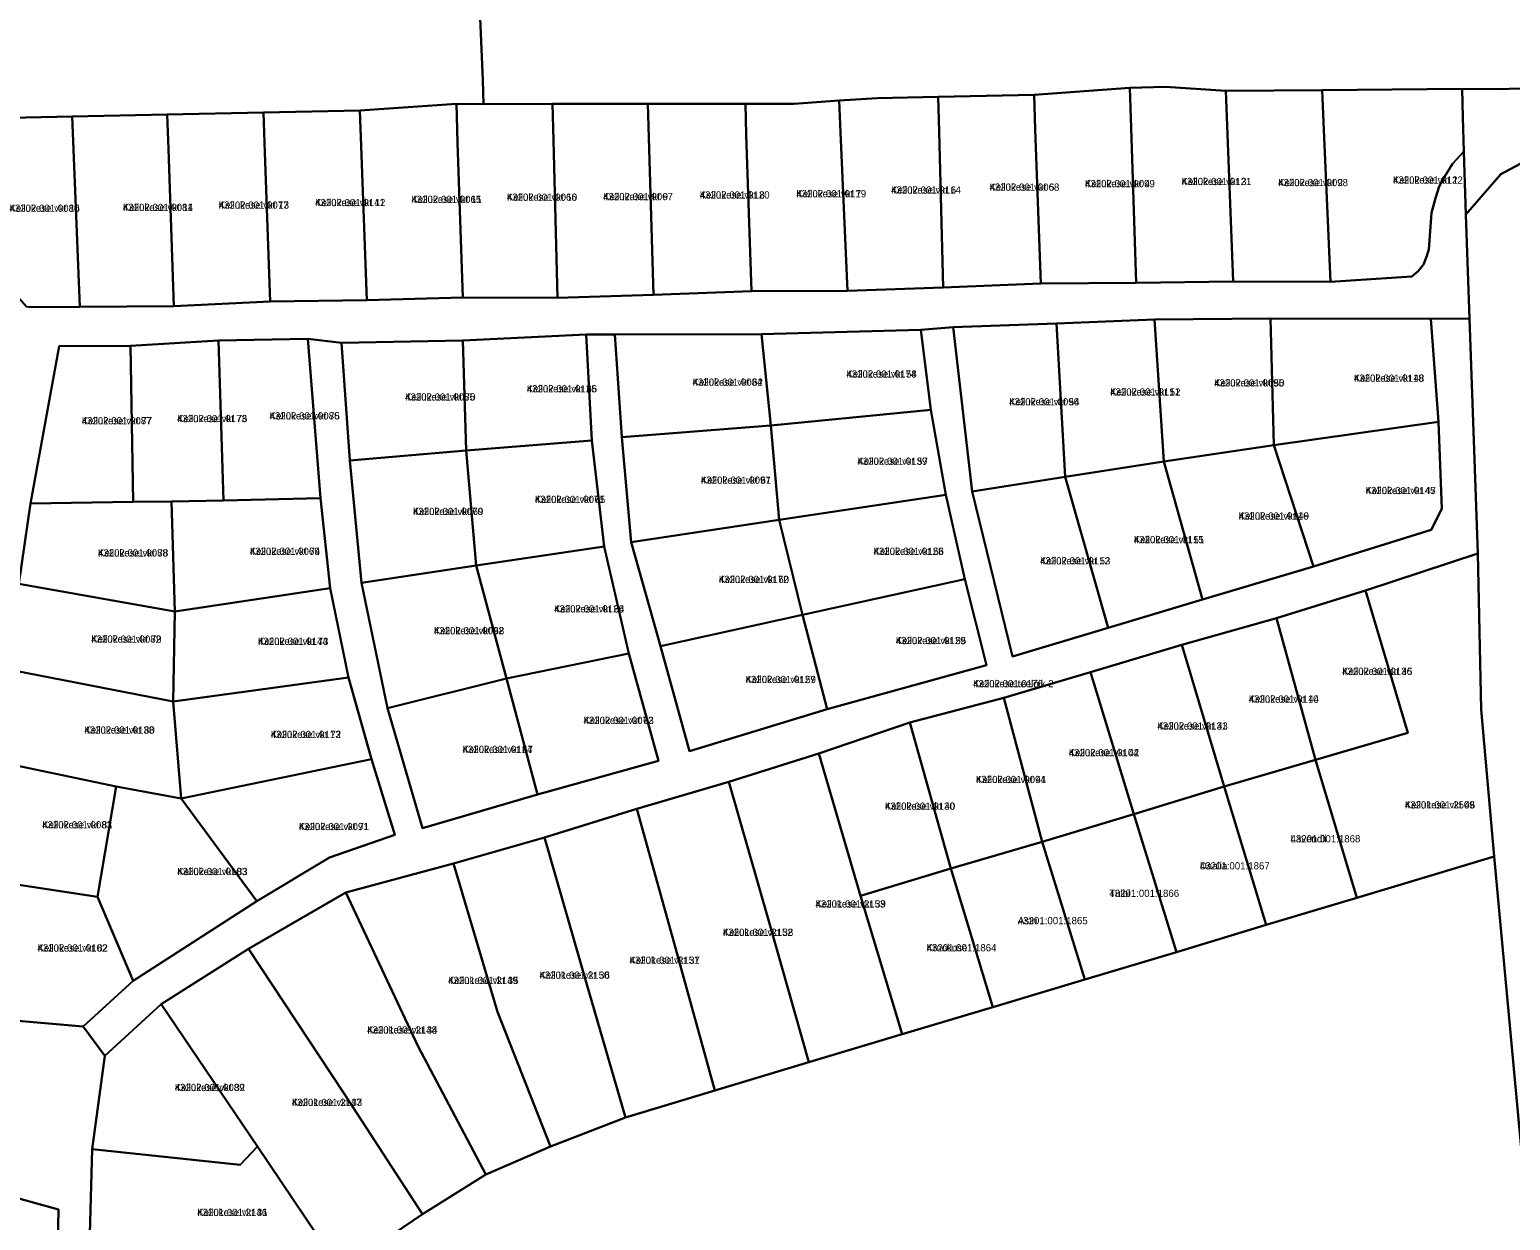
# Model space of a CAD drawing. Extents: x 661852 to 683758, y 6469495 to 6482657.
# Drawn here: x 665720.1 to 666027.7, y 6471512.2 to 6471759.5 of the extents above; entities that cross this region are included whole.
import ezdxf

# ---------------------------------------------------------------- set-up
doc = ezdxf.new("R2010")
doc.units = 0
for name, color, linetype in [('L_AADRESS', 7, 'Continuous'), ('PIIR', 7, 'Continuous'), ('TUNNUS', 7, 'Continuous')]:
    doc.layers.add(name, color=color, linetype=linetype)

msp = doc.modelspace()

# ---------------------------------------------------------------- linework, layer by layer
at = {"layer": 'PIIR'}
for points in [[(665812.89, 6471779.74), (665814.19, 6471749.05), (665814.38, 6471744.07), (665808.72, 6471744.08), (665788.69, 6471742.75), (665768.63, 6471742.33), (665748.66, 6471741.91), (665728.91, 6471741.5), (665693.53, 6471740.75), (665686.99, 6471739.11), (665686.19, 6471738.96), (665684.92, 6471737.76), (665684.4, 6471741.78), (665672.39, 6471830.94)], [(666188.02, 6471764.83), (666128.13, 6471758.72), (666113.14, 6471755.77), (666050.75, 6471747.95), (666025.02, 6471747.15), (666017.63, 6471747.2), (665988.57, 6471746.94), (665968.56, 6471746.79), (665956.01, 6471747.64), (665948.6, 6471747.42), (665928.71, 6471745.98), (665908.82, 6471745.56), (665896.11, 6471745.3), (665888.22, 6471744.84), (665878.88, 6471744.1), (665868.75, 6471744.1), (665848.52, 6471744.09), (665828.69, 6471744.08), (665814.38, 6471744.07), (665814.19, 6471749.05), (665812.89, 6471779.74)], [(665719.91, 6471701.87), (665730.5, 6471701.93), (665750.04, 6471702.1), (665770.07, 6471703.06), (665790.12, 6471703.32), (665810.09, 6471703.93), (665829.73, 6471703.84), (665849.7, 6471704.44), (665870.04, 6471705.23), (665889.94, 6471705.28), (665909.81, 6471705.96), (665930.12, 6471706.78), (665949.89, 6471706.94), (665970.09, 6471707.22), (665990.27, 6471707.12), (666007.18, 6471708.27), (666008.51, 6471709.36), (666009.57, 6471710.73), (666010.26, 6471712.33), (666010.68, 6471713.89), (666011.26, 6471721.47), (666012.08, 6471724.55), (666012.85, 6471726.94), (666013.95, 6471728.98), (666015.61, 6471731.65), (666017.96, 6471734.19), (666018.41, 6471721.13), (666019.17, 6471699.51), (666011.1, 6471699.5), (665977.85, 6471699.55), (665953.7, 6471699.36), (665933.37, 6471698.49), (665911.89, 6471697.72), (665905.17, 6471697.16), (665872.12, 6471696.29), (665841.66, 6471696.19), (665835.7, 6471696.23), (665810.06, 6471694.98), (665784.88, 6471694.49), (665777.87, 6471695.33), (665759.33, 6471694.97), (665741.07, 6471693.86), (665726.19, 6471693.81), (665720.26, 6471661.11), (665717.86, 6471644.43)], [(665784.67, 6471501.96), (665801.72, 6471513.57), (665814.83, 6471521.75), (665828.25, 6471527.62), (665843.84, 6471533.6), (665862.39, 6471539.22), (665881.96, 6471545.09), (665901.3, 6471550.89), (665920.12, 6471556.52), (665939.25, 6471562.26), (665958.29, 6471567.98), (665976.92, 6471573.6), (665995.76, 6471579.25), (666024.31, 6471587.84), (666030.99, 6471515.35)], [(665702.43, 6471554.99), (665731.2, 6471552.53), (665735.71, 6471546.41), (665733.06, 6471527.07), (665732.32, 6471499.43)], [(665725.28, 6471473.59), (665726.1, 6471514.53), (665717.83, 6471516.78)]]:
    msp.add_lwpolyline(points, dxfattribs=at)
for points in [[(666017.63, 6471747.2), (666025.02, 6471747.15), (666050.75, 6471747.95), (666113.14, 6471755.77), (666128.13, 6471758.72), (666188.02, 6471764.83), (666192.34, 6471742.07), (666186.44, 6471748), (666177.54, 6471750.16), (666147.11, 6471747.24), (666103.66, 6471742.46), (666035.88, 6471735), (666025.65, 6471729.5), (666018.41, 6471721.13), (666017.96, 6471734.19), (666017.77, 6471741.3)], [(665909.81, 6471705.96), (665909, 6471738.38), (665908.82, 6471745.56), (665928.71, 6471745.98), (665928.97, 6471738.76), (665930.11, 6471706.78)], [(665930.11, 6471706.78), (665928.97, 6471738.76), (665928.71, 6471745.98), (665948.6, 6471747.42), (665948.91, 6471739.16), (665949.89, 6471706.94)], [(665949.89, 6471706.94), (665948.91, 6471739.16), (665948.6, 6471747.42), (665956.01, 6471747.64), (665968.56, 6471746.79), (665968.83, 6471739.62), (665970.09, 6471707.22)], [(665970.09, 6471707.22), (665968.83, 6471739.62), (665968.56, 6471746.79), (665988.57, 6471746.94), (665988.85, 6471740.33), (665990.27, 6471707.12)], [(665990.27, 6471707.12), (665988.85, 6471740.33), (665988.57, 6471746.94), (666017.63, 6471747.2), (666017.77, 6471741.3), (666017.96, 6471734.19), (666015.61, 6471731.65), (666013.95, 6471728.98), (666012.85, 6471726.94), (666012.08, 6471724.55), (666011.26, 6471721.47), (666010.68, 6471713.89), (666010.26, 6471712.33), (666009.57, 6471710.73), (666008.51, 6471709.36), (666007.18, 6471708.27)], [(665770.07, 6471703.06), (665768.94, 6471734.02), (665768.63, 6471742.33), (665788.69, 6471742.75), (665788.96, 6471735.32), (665790.12, 6471703.32)], [(665790.12, 6471703.32), (665788.96, 6471735.32), (665788.69, 6471742.75), (665808.72, 6471744.08), (665808.96, 6471736.03), (665810.09, 6471703.93)], [(665810.09, 6471703.93), (665808.96, 6471736.03), (665808.72, 6471744.08), (665814.38, 6471744.07), (665828.69, 6471744.08), (665828.9, 6471736.49), (665829.73, 6471703.84)], [(665829.73, 6471703.84), (665828.9, 6471736.49), (665828.69, 6471744.08), (665848.52, 6471744.09), (665848.73, 6471737.02), (665849.7, 6471704.44)], [(665849.7, 6471704.44), (665848.73, 6471737.02), (665848.52, 6471744.09), (665868.75, 6471744.1), (665868.95, 6471737.65), (665870.04, 6471705.23)], [(665889.94, 6471705.28), (665870.04, 6471705.23), (665868.95, 6471737.65), (665868.75, 6471744.1), (665878.88, 6471744.1), (665888.22, 6471744.84), (665888.51, 6471738.14)], [(665889.94, 6471705.28), (665888.51, 6471738.14), (665888.22, 6471744.84), (665896.11, 6471745.3), (665908.82, 6471745.56), (665909, 6471738.38), (665909.81, 6471705.96)], [(665719.91, 6471701.87), (665719.44, 6471701.97), (665691.18, 6471734.14), (665686.99, 6471739.11), (665693.53, 6471740.75), (665728.91, 6471741.5), (665729.19, 6471734.62), (665730.5, 6471701.93)], [(665730.5, 6471701.93), (665729.19, 6471734.62), (665728.91, 6471741.5), (665748.66, 6471741.91), (665748.91, 6471734.69), (665750.04, 6471702.1)], [(665750.04, 6471702.1), (665748.91, 6471734.69), (665748.66, 6471741.91), (665768.63, 6471742.33), (665768.94, 6471734.02), (665770.07, 6471703.06)], [(666019.17, 6471699.51), (666018.41, 6471721.13), (666025.65, 6471729.5), (666035.88, 6471735), (666103.66, 6471742.46), (666119.96, 6471639.91), (666134.37, 6471549.3), (666030.99, 6471515.35), (666024.31, 6471587.84), (666021.56, 6471618.31), (666020.87, 6471650.74)], [(665741.58, 6471562.02), (665767.3, 6471578.54), (665782.4, 6471587.6), (665795.91, 6471592.33), (665791.07, 6471608.04), (665786.35, 6471624.99), (665782.48, 6471643.51), (665780.53, 6471662.23), (665777.87, 6471695.33), (665784.88, 6471694.49), (665786.57, 6471670.02), (665788.99, 6471644.66), (665794.44, 6471618.63), (665801.67, 6471593.69), (665825.6, 6471600.66), (665850.7, 6471607.71), (665844.52, 6471630), (665839.41, 6471652.22), (665836.83, 6471674.23), (665835.7, 6471696.23), (665841.66, 6471696.19), (665843.06, 6471674.86), (665845.06, 6471653.09), (665851.14, 6471631.5), (665857.14, 6471609.7), (665885.76, 6471618.43), (665918.86, 6471627.53), (665914.34, 6471645.39), (665910.41, 6471662.92), (665907.27, 6471680.57), (665905.17, 6471697.16), (665911.89, 6471697.72), (665915.83, 6471663.61), (665924.21, 6471629.38), (665944.1, 6471635.31), (665963.69, 6471641.15), (665986.77, 6471648.03), (666011.2, 6471655.66), (666013.43, 6471660.01), (666012.75, 6471678.11), (666011.1, 6471699.5), (666019.17, 6471699.51), (666020.87, 6471650.74), (665997.58, 6471643.03), (665979.06, 6471637.28), (665959.44, 6471631.79), (665940.45, 6471626.06), (665922.46, 6471620.79), (665902.92, 6471615.62), (665884.04, 6471609.17), (665865.35, 6471603.3), (665846.22, 6471597.68), (665827, 6471591.75), (665808.13, 6471586.34), (665785.75, 6471580.31), (665765.56, 6471568.66), (665747.38, 6471557.17), (665735.71, 6471546.41), (665731.2, 6471552.53)], [(665907.27, 6471680.57), (665874.07, 6471677.35), (665872.12, 6471696.29), (665905.17, 6471697.16)], [(665933.37, 6471698.49), (665935.2, 6471666.68), (665915.83, 6471663.61), (665911.89, 6471697.72)], [(665953.7, 6471699.36), (665955.67, 6471669.82), (665935.2, 6471666.68), (665933.37, 6471698.49)], [(665977.85, 6471699.55), (665978.52, 6471673.25), (665955.67, 6471669.82), (665953.7, 6471699.36)], [(666011.1, 6471699.5), (666012.75, 6471678.11), (665978.52, 6471673.25), (665977.85, 6471699.55)], [(665726.19, 6471693.81), (665741.07, 6471693.86), (665741.56, 6471661.43), (665720.26, 6471661.11)], [(665759.33, 6471694.97), (665760.35, 6471661.74), (665749.56, 6471661.56), (665741.56, 6471661.43), (665741.07, 6471693.86)], [(665777.87, 6471695.33), (665780.53, 6471662.23), (665760.35, 6471661.74), (665759.33, 6471694.97)], [(665784.88, 6471694.49), (665810.06, 6471694.98), (665810.75, 6471672.15), (665786.57, 6471670.02)], [(665835.7, 6471696.23), (665836.83, 6471674.23), (665810.75, 6471672.15), (665810.06, 6471694.98)], [(665841.66, 6471696.19), (665872.12, 6471696.29), (665874.07, 6471677.35), (665843.06, 6471674.86)], [(665910.41, 6471662.92), (665875.74, 6471657.72), (665874.07, 6471677.35), (665907.27, 6471680.57)], [(665843.06, 6471674.86), (665874.07, 6471677.35), (665875.74, 6471657.72), (665845.06, 6471653.09)], [(665986.77, 6471648.03), (665978.52, 6471673.25), (666012.75, 6471678.11), (666013.43, 6471660.01), (666011.2, 6471655.66)], [(665786.57, 6471670.02), (665810.75, 6471672.15), (665812.87, 6471648.21), (665788.99, 6471644.66)], [(665839.41, 6471652.22), (665812.87, 6471648.21), (665810.75, 6471672.15), (665836.83, 6471674.23)], [(665963.69, 6471641.15), (665955.67, 6471669.82), (665978.52, 6471673.25), (665986.77, 6471648.03)], [(665944.1, 6471635.31), (665935.2, 6471666.68), (665955.67, 6471669.82), (665963.69, 6471641.15)], [(665915.83, 6471663.61), (665935.2, 6471666.68), (665944.1, 6471635.31), (665924.21, 6471629.38)], [(665914.34, 6471645.39), (665880.65, 6471637.97), (665875.74, 6471657.72), (665910.41, 6471662.92)], [(665720.26, 6471661.11), (665741.56, 6471661.43), (665749.56, 6471661.56), (665750.25, 6471638.66), (665717.85, 6471644.43)], [(665782.48, 6471643.51), (665750.25, 6471638.66), (665749.56, 6471661.56), (665760.35, 6471661.74), (665780.53, 6471662.23)], [(665845.06, 6471653.09), (665875.74, 6471657.72), (665880.65, 6471637.97), (665851.14, 6471631.5)], [(665844.52, 6471630), (665819.14, 6471624.77), (665812.87, 6471648.21), (665839.41, 6471652.22)], [(666006.35, 6471613.51), (665997.58, 6471643.03), (666020.87, 6471650.74), (666021.56, 6471618.31), (666024.31, 6471587.84), (665995.76, 6471579.25), (665987.16, 6471607.88)], [(665788.99, 6471644.66), (665812.87, 6471648.21), (665819.14, 6471624.77), (665794.44, 6471618.63)], [(665717.85, 6471644.43), (665750.25, 6471638.66), (665749.89, 6471619.98), (665714.66, 6471626.82)], [(665885.76, 6471618.43), (665880.65, 6471637.97), (665914.34, 6471645.39), (665918.86, 6471627.53)], [(665786.35, 6471624.99), (665749.89, 6471619.98), (665750.25, 6471638.66), (665782.48, 6471643.51)], [(665987.16, 6471607.88), (665979.06, 6471637.28), (665997.58, 6471643.03), (666006.35, 6471613.51)], [(665851.14, 6471631.5), (665880.65, 6471637.97), (665885.76, 6471618.43), (665857.14, 6471609.7)], [(665968.23, 6471602.38), (665959.44, 6471631.79), (665979.06, 6471637.28), (665987.16, 6471607.88)], [(665825.6, 6471600.66), (665819.14, 6471624.77), (665844.52, 6471630), (665850.7, 6471607.71)], [(665949.41, 6471596.57), (665940.45, 6471626.06), (665959.44, 6471631.79), (665968.23, 6471602.38)], [(665714.66, 6471626.82), (665749.89, 6471619.98), (665751.55, 6471599.84), (665738.07, 6471602.37), (665711.59, 6471607.86)], [(665930.38, 6471590.89), (665922.46, 6471620.79), (665940.45, 6471626.06), (665949.41, 6471596.57)], [(665791.07, 6471608.04), (665751.55, 6471599.84), (665749.89, 6471619.98), (665786.35, 6471624.99)], [(665801.67, 6471593.69), (665794.44, 6471618.63), (665819.14, 6471624.77), (665825.6, 6471600.66)], [(665911.45, 6471585.35), (665902.92, 6471615.62), (665922.46, 6471620.79), (665930.38, 6471590.89)], [(665892.69, 6471579.66), (665884.04, 6471609.17), (665902.92, 6471615.62), (665911.45, 6471585.35)], [(665711.59, 6471607.86), (665738.07, 6471602.37), (665734.21, 6471579.45), (665706.84, 6471583.61)], [(665782.4, 6471587.6), (665767.3, 6471578.54), (665751.55, 6471599.84), (665791.07, 6471608.04), (665795.91, 6471592.33)], [(665873.65, 6471574.37), (665865.35, 6471603.3), (665884.04, 6471609.17), (665892.69, 6471579.66), (665901.3, 6471550.89), (665881.96, 6471545.09)], [(665976.92, 6471573.6), (665968.23, 6471602.38), (665987.16, 6471607.88), (665995.76, 6471579.25)], [(665741.58, 6471562.02), (665734.21, 6471579.45), (665738.07, 6471602.37), (665751.55, 6471599.84), (665767.3, 6471578.54)], [(665854.29, 6471568.57), (665846.22, 6471597.68), (665865.35, 6471603.3), (665873.65, 6471574.37), (665881.96, 6471545.09), (665862.39, 6471539.22)], [(665958.29, 6471567.98), (665949.41, 6471596.57), (665968.23, 6471602.38), (665976.92, 6471573.6)], [(665835.7, 6471561.73), (665827, 6471591.75), (665846.22, 6471597.68), (665854.29, 6471568.57), (665862.39, 6471539.22), (665843.84, 6471533.6)], [(665939.25, 6471562.26), (665930.38, 6471590.89), (665949.41, 6471596.57), (665958.29, 6471567.98)], [(665817.3, 6471555.57), (665808.13, 6471586.34), (665827, 6471591.75), (665835.7, 6471561.73), (665843.84, 6471533.6), (665828.25, 6471527.62)], [(665920.12, 6471556.52), (665911.45, 6471585.35), (665930.38, 6471590.89), (665939.25, 6471562.26)], [(665800.81, 6471548.37), (665785.75, 6471580.31), (665808.13, 6471586.34), (665817.3, 6471555.57), (665828.25, 6471527.62), (665814.83, 6471521.75)], [(665706.84, 6471583.61), (665734.21, 6471579.45), (665741.58, 6471562.02), (665731.2, 6471552.53), (665702.43, 6471554.99)], [(665901.3, 6471550.89), (665892.69, 6471579.66), (665911.45, 6471585.35), (665920.12, 6471556.52)], [(665785.32, 6471538.68), (665765.56, 6471568.66), (665785.75, 6471580.31), (665800.81, 6471548.37), (665814.83, 6471521.75), (665801.72, 6471513.57)], [(665767.41, 6471527.59), (665747.38, 6471557.17), (665765.56, 6471568.66), (665785.32, 6471538.68), (665801.72, 6471513.57), (665784.67, 6471501.96)], [(665735.71, 6471546.41), (665747.38, 6471557.17), (665767.41, 6471527.59), (665763.85, 6471523.8), (665733.06, 6471527.07)], [(665732.32, 6471499.43), (665733.06, 6471527.07), (665763.85, 6471523.8), (665767.41, 6471527.59), (665784.67, 6471501.96), (665779.93, 6471498.71), (665759.93, 6471499.05)], [(665726.1, 6471514.53), (665725.28, 6471473.59), (665701.12, 6471486.1), (665696.35, 6471486.42), (665717.83, 6471516.78)]]:
    msp.add_lwpolyline(points, close=True, dxfattribs=at)

# ---------------------------------------------------------------- texts
at = {"layer": 'L_AADRESS'}
for s, p in [('Kellukese vkt 5', (665919.46, 6471726.07)), ('Kellukese vkt 4', (665939.3, 6471726.8)), ('Kellukese vkt 3', (665959.35, 6471727.24)), ('Kellukese vkt 2', (665979.42, 6471727.02)), ('Kellukese vkt 1', (666003.27, 6471727.54)), ('Kellukese vkt 12', (665779.38, 6471722.87)), ('Kellukese vkt 11', (665799.39, 6471723.53)), ('Kellukese vkt 10', (665819.22, 6471723.98)), ('Kellukese vkt 9', (665839.2, 6471724.1)), ('Kellukese vkt 8', (665859.28, 6471724.45)), ('Kellukese vkt 7', (665879.34, 6471724.7)), ('Kellukese vkt 6', (665899.02, 6471725.47)), ('Kellukese vkt 15', (665715.91, 6471721.69)), ('Kellukese vkt 14', (665739.47, 6471721.86)), ('Kellukese vkt 13', (665759.36, 6471722.34)), ('Kellukese vkt 58', (665889.74, 6471687.26)), ('Kellukese vkt 48', (665995.15, 6471686.4)), ('Kellukese vkt 66', (665823.35, 6471684.19)), ('Kellukese vkt 62', (665857.79, 6471685.57)), ('Kellukese vkt 52', (665944.52, 6471683.54)), ('Kellukese vkt 50', (665966.11, 6471685.42)), ('Kellukese vkt 70', (665798.07, 6471682.5)), ('Kellukese vkt 54', (665923.55, 6471681.49)), ('Kellukese vkt 77', (665730.91, 6471677.55)), ('Kellukese vkt 76', (665750.71, 6471678.01)), ('Kellukese vkt 75', (665769.93, 6471678.57)), ('Kellukese vkt 57', (665892.04, 6471669.15)), ('Kellukese vkt 61', (665859.52, 6471665.22)), ('Kellukese vkt 65', (665825.04, 6471661.22)), ('Kellukese vkt 47', (665997.58, 6471663.07)), ('Kellukese vkt 69', (665799.72, 6471658.72)), ('Kellukese vkt 49', (665971.22, 6471657.77)), ('Kellukese vkt 51', (665949.45, 6471652.88)), ('Kellukese vkt 78', (665734.29, 6471650.11)), ('Kellukese vkt 74', (665765.83, 6471650.45)), ('Kellukese vkt 56', (665895.38, 6471650.45)), ('Kellukese vkt 53', (665929.96, 6471648.47)), ('Kellukese vkt 60', (665863.22, 6471644.61)), ('Kellukese vkt 64', (665829.02, 6471638.49)), ('Kellukese vkt 68', (665804.07, 6471633.96)), ('Kellukese vkt 79', (665732.88, 6471632.21)), ('Kellukese vkt 73', (665767.53, 6471631.75)), ('Kellukese vkt 55', (665899.99, 6471631.91)), ('Kellukese vkt 45', (665992.71, 6471625.51)), ('Kellukese vkt 59', (665868.8, 6471623.83)), ('Kellukese teelõik 2', (665916.05, 6471622.96)), ('Kellukese vkt 44', (665973.3, 6471619.76)), ('Kellukese vkt 63', (665835.13, 6471615.33)), ('Kellukese vkt 80', (665731.46, 6471613.33)), ('Kellukese vkt 72', (665770.18, 6471612.41)), ('Kellukese vkt 43', (665954.34, 6471614.17)), ('Kellukese vkt 67', (665810.02, 6471609.31)), ('Kellukese vkt 42', (665935.93, 6471608.64)), ('Kellukese vkt 41', (665916.65, 6471603.06)), ('Kellukese vkt 40', (665897.75, 6471597.52)), ('Kellukese vkt 46', (666005.73, 6471597.79)), ('Kellukese vkt 81', (665722.7, 6471593.65)), ('Kellukese vkt 71', (665776, 6471593.29)), ('Lavendli', (665981.99, 6471590.75)), ('Daalia', (665963.16, 6471585.13)), ('Kellukese vkt 83', (665750.75, 6471583.95)), ('Tulbi', (665944.34, 6471579.42)), ('Kellukese vkt 39', (665883.32, 6471577.22)), ('Astri', (665925.35, 6471573.75)), ('Kellukese vkt 38', (665864.09, 6471571.33)), ('Kellukese vkt 82', (665721.73, 6471568.07)), ('Krookuse', (665906.4, 6471568.12)), ('Kellukese vkt 37', (665844.7, 6471565.53)), ('Kellukese vkt 35', (665807, 6471561.33)), ('Kellukese vkt 36', (665825.99, 6471562.43)), ('Kellukese vkt 34', (665790.2, 6471551.05)), ('Kellukese vkt 32', (665750.23, 6471539.1)), ('Kellukese vkt 33', (665774.55, 6471536)), ('Kellukese vkt 31', (665754.91, 6471513.15))]:
    msp.add_text(s, height=1.5, dxfattribs=at).set_placement(p)
at = {"layer": 'TUNNUS'}
for s, p in [('43202:001:0068', (665919.46, 6471726.07)), ('43202:001:0099', (665939.3, 6471726.8)), ('43202:001:0121', (665959.35, 6471727.24)), ('43202:001:0098', (665979.42, 6471727.02)), ('43202:001:0122', (666003.27, 6471727.54)), ('43202:001:0141', (665779.38, 6471722.87)), ('43202:001:0065', (665799.39, 6471723.53)), ('43202:001:0066', (665819.22, 6471723.98)), ('43202:001:0067', (665839.2, 6471724.1)), ('43202:001:0120', (665859.28, 6471724.45)), ('43202:001:0119', (665879.34, 6471724.7)), ('43202:001:0114', (665899.02, 6471725.47)), ('43202:001:0080', (665715.91, 6471721.69)), ('43202:001:0081', (665739.47, 6471721.86)), ('43202:001:0077', (665759.36, 6471722.34)), ('43202:001:0174', (665889.74, 6471687.26)), ('43202:001:0118', (665995.15, 6471686.4)), ('43202:001:0125', (665823.35, 6471684.19)), ('43202:001:0084', (665857.79, 6471685.57)), ('43202:001:0111', (665944.52, 6471683.54)), ('43202:001:0095', (665966.11, 6471685.42)), ('43202:001:0085', (665798.07, 6471682.5)), ('43202:001:0096', (665923.55, 6471681.49)), ('43202:001:0087', (665730.91, 6471677.55)), ('43202:001:0173', (665750.71, 6471678.01)), ('43202:001:0086', (665769.93, 6471678.57)), ('43202:001:0139', (665892.04, 6471669.15)), ('43202:001:0097', (665859.52, 6471665.22)), ('43202:001:0145', (665997.58, 6471663.07)), ('43202:001:0070', (665799.72, 6471658.72)), ('43202:001:0071', (665825.04, 6471661.22)), ('43202:001:0116', (665971.22, 6471657.77)), ('43202:001:0115', (665949.45, 6471652.88)), ('43202:001:0088', (665734.29, 6471650.11)), ('43202:001:0069', (665765.83, 6471650.45)), ('43202:001:0128', (665895.38, 6471650.45)), ('43202:001:0112', (665929.96, 6471648.47)), ('43202:001:0172', (665863.22, 6471644.61)), ('43202:001:0126', (665829.02, 6471638.49)), ('43202:001:0092', (665804.07, 6471633.96)), ('43202:001:0082', (665732.88, 6471632.21)), ('43202:001:0144', (665767.53, 6471631.75)), ('43202:001:0129', (665899.99, 6471631.91)), ('43202:001:0136', (665992.71, 6471625.51)), ('43202:001:0127', (665868.8, 6471623.83)), ('43202:001:0176', (665916.05, 6471622.96)), ('43202:001:0110', (665973.3, 6471619.76)), ('43202:001:0072', (665835.13, 6471615.33)), ('43202:001:0138', (665731.46, 6471613.33)), ('43202:001:0113', (665770.18, 6471612.41)), ('43202:001:0131', (665954.34, 6471614.17)), ('43202:001:0124', (665810.02, 6471609.31)), ('43202:001:0104', (665935.93, 6471608.64)), ('43202:001:0094', (665916.65, 6471603.06)), ('43202:001:0130', (665897.75, 6471597.52)), ('43201:001:2509', (666005.73, 6471597.79)), ('43202:001:0083', (665722.7, 6471593.65)), ('43202:001:0091', (665776, 6471593.29)), ('43201:001:1868', (665981.99, 6471590.75)), ('43201:001:1867', (665963.16, 6471585.13)), ('43202:001:0103', (665750.75, 6471583.95)), ('43201:001:1866', (665944.34, 6471579.42)), ('43201:001:2153', (665883.32, 6471577.22)), ('43201:001:1865', (665925.35, 6471573.75)), ('43201:001:2152', (665864.09, 6471571.33)), ('43202:001:0102', (665721.73, 6471568.07)), ('43201:001:1864', (665906.4, 6471568.12)), ('43201:001:2151', (665844.7, 6471565.53)), ('43201:001:2149', (665807, 6471561.33)), ('43201:001:2150', (665825.99, 6471562.43)), ('43201:001:2148', (665790.2, 6471551.05)), ('43202:001:0089', (665750.23, 6471539.1)), ('43201:001:2147', (665774.55, 6471536)), ('43201:001:2146', (665754.91, 6471513.15))]:
    msp.add_text(s, height=1.5, dxfattribs=at).set_placement(p)

doc.saveas('drawing.dxf')
